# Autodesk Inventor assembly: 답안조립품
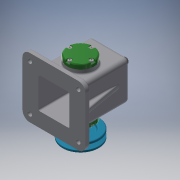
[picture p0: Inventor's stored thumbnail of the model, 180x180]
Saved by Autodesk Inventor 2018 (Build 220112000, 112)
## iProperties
Created: 2022-11
Part Number: 답안조립품
Material: 일반
Document SubType Name: Assembly
Designer: home
Author: home
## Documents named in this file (16)
- C:\Users\kimgi\Desktop\721106V1006\답안조립품.iam
- C:\Users\kimgi\Desktop\721106V1006\본체.ipt
- C:\Users\kimgi\Desktop\721106V1006\앞커버.ipt
- C:\Users\kimgi\Desktop\721106V1006\뒤커버.ipt
- C:\Users\kimgi\Desktop\721106V1006\베어링 6201.ipt
- C:\Users\kimgi\Desktop\721106V1006\편심축.ipt
- C:\Users\kimgi\Desktop\721106V1006\오일실 12 25 7.ipt
- C:\Users\kimgi\Desktop\721106V1006\V벨트풀리.ipt
- C:\Users\kimgi\Desktop\721106V1006\키 4 x 4 x 15.ipt
- C:\Users\kimgi\Desktop\721106V1006\멈춤나사 M3 x 8.ipt
- C:\Users\kimgi\Desktop\721106V1006\볼트 M4 x 12.ipt
- C:\Users\kimgi\Desktop\721106V1006\링크.ipt
- C:\Users\kimgi\Desktop\721106V1006\슬라이드.ipt
- C:\Users\kimgi\Desktop\721106V1006\핀 5 x 18.ipt
- C:\Users\kimgi\Desktop\721106V1006\고정핀 1.2 x 10.ipt
- C:\Users\kimgi\Desktop\721106V1006\부시.ipt
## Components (11 placed, 4 different names)
1. V벨트풀리:1 — 각도:2
2. ISO 4762 M4 x 12:1
3. ISO 4762 M4 x 12:2
4. ISO 4762 M4 x 12:3
5. ISO 4762 M4 x 12:4
6. ISO 4762 M4 x 12:5
7. ISO 4762 M4 x 12:6
8. ISO 4762 M4 x 12:7
9. ISO 4762 M4 x 12:8
10. 핀 5 x 18:1
11. 고정핀 1.2 x 10:1
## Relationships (1: Angle 1)
- 각도:2 [Angle]: V벨트풀리:1
